Omron Sysmac Studio project OCR_V460H_Example_1.0 (Sysmac Studio 1.54.0.64019, StandardProject)
(* V460-H Application Program Example, based on OCR V460-H Function Blocks (OCR_V460H Library). *)

# Controller new_Controller_0: NX1P2-9024DT1 version 1.46
Task PrimaryTask (priority 4, period or condition 2000): Prg_OCR_V460_All
Library OCR_V460H 1.0.0 (contents left out)

VAR_GLOBAL
    OUT_B00 : BOOL;  (* Output Bit 00 (YELLOW); at BuiltInIO://cpu/#0/Output_Bit_00 *)
    OUT_B01 : BOOL;  (* Output Bit 01 (RED); at BuiltInIO://cpu/#0/Output_Bit_01 *)
    OUT_B02 : BOOL;  (* Output Bit 02 (GREEN); at BuiltInIO://cpu/#0/Output_Bit_02 *)
    V460_01_IN_100 : s_V460_IN_100;  (* EtherNet/IP Input - Assembly 100; network input *)
    V460_01_IN_101 : s_V460_IN_101;  (* EtherNet/IP Input - Assembly 101; network input *)
    V460_01_IN_102 : s_V460_IN_102;  (* EtherNet/IP Input - Assembly 102; network input *)
    V460_01_IN_103 : s_V460_IN_103;  (* EtherNet/IP Input - Assembly 103; network input *)
    V460_01_IN_104 : s_V460_IN_104;  (* EtherNet/IP Input - Assembly 104; network input *)
    V460_01_IN_105 : s_V460_IN_105;  (* EtherNet/IP Input - Assembly 105; network input *)
    V460_01_OUT_197 : s_V460_OUT_197;  (* EtherNet/IP Output - Assembly 197; network output *)
    V460_01_OUT_198 : s_V460_OUT_198;  (* EtherNet/IP Output - Assembly 198; network output *)
    V460_01_Reader_IN : s_V460_Reader_IN := (Reader_IPAddress := '192.168.188.2', Reader_Trigger := False, Reader_ClearCounterNoRead := False, Reader_ClearCounterMatchcode := False);  (* Reader - Input (User) *)
    V460_01_Reader_OUT : s_V460_Reader_OUT;  (* Reader - Output (User) *)
    V460_01_KCommand : s_V460_KCommand;  (* V460-H K Command (User) *)
    V460_01_Control : s_V460_Control;  (* V460-H Control *)
    V460_01_Lighting : s_V460_Lighting;  (* V460-H Lighting *)
    V460_01_Settings : s_V460_Settings;  (* V460-H Settings *)
    V460_01_Database : s_V460_Database;  (* V460-H Database *)
    V460_01_Lighting_HMI : s_V460_Lighting_HMI;  (* V460-H Lighting (HMI) *)
END_VAR

PROGRAM Prg_OCR_V460
VAR
    V460_01_Enable : BOOL := True;  (* V460-H Enable *)
    V460_01_Connected : BOOL;  (* V460-H Connected *)
    V460_01_Busy : BOOL;  (* V460-H Busy *)
    V460_01_Done : BOOL;  (* V460-H Done (Read Cycle Pass) *)
    V460_01_Error : BOOL;  (* V460-H Error (Read Cycle Fail) *)
    V460_01_DecodeLength : UINT;  (* V460-H Decode Length *)
    V460_01_DecodeData : STRING[184];  (* V460-H Decode Data *)
    V460_01_FB_EIP : OCR_V460_EIP;
    V460_01_Timer_ON : TON;  (* V460-H Timer *)
    V460_01_Time_ON : TIME := TIME#200ms;  (* V460-H Time *)
    V460_01_Counter_NoReadCycle : DINT;  (* V460-H Counter No Read Cycle *)
    V460_01_Counter_NoRead : UDINT;  (* V460-H Counter No Read *)
    V460_01_Counter_MismatchCycle : DINT;  (* V460-H Counter Mismatch Cycle *)
    V460_01_Counter_Trigger : UDINT;  (* V460-H Counter Trigger *)
    V460_01_Counter_Matchcode : UDINT;  (* V460-H Counter Matchcode *)
    V460_01_Counter_Mismatch : UDINT;  (* V460-H Counter Mismatch *)
    V460_01_Time_ReadCycleTotal : INT;  (* V460-H Time Read Cycle Total *)
END_VAR
VAR_EXTERNAL
    OUT_B00 : BOOL;
    OUT_B01 : BOOL;
    V460_01_IN_102 : s_V460_IN_102;
    V460_01_OUT_197 : s_V460_OUT_197;
    V460_01_Reader_IN : s_V460_Reader_IN;
    V460_01_Reader_OUT : s_V460_Reader_OUT;
    OUT_B02 : BOOL;
END_VAR

(* Section Prg_OCR_V460: ladder, written here as Structured Text *)

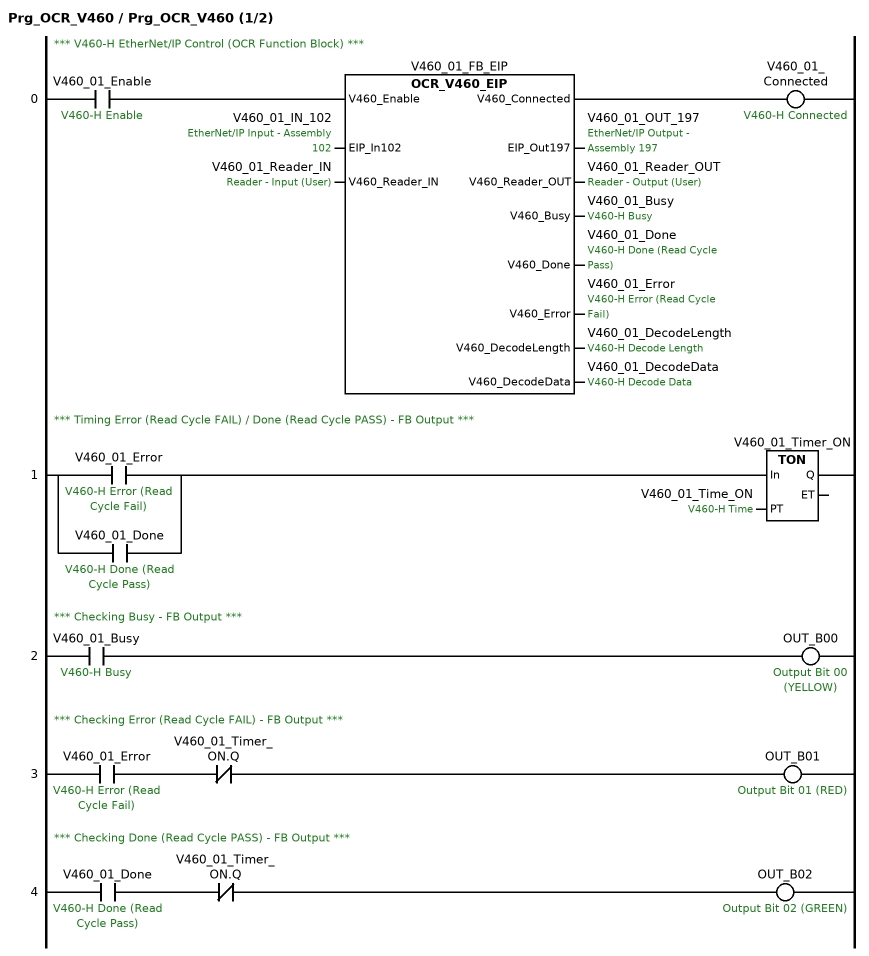
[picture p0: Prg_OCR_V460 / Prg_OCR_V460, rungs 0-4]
(* Rung 0: *** V460-H EtherNet/IP Control (OCR Function Block) *** *)
V460_01_FB_EIP(V460_Enable := V460_01_Enable, EIP_In102 := V460_01_IN_102, V460_Reader_IN := V460_01_Reader_IN, EIP_Out197 => V460_01_OUT_197, V460_Reader_OUT => V460_01_Reader_OUT, V460_Busy => V460_01_Busy, V460_Done => V460_01_Done, V460_Error => V460_01_Error, V460_DecodeLength => V460_01_DecodeLength, V460_DecodeData => V460_01_DecodeData);
V460_01_Connected := V460_01_FB_EIP.V460_Connected;
(* Rung 1: *** Timing Error (Read Cycle FAIL) / Done (Read Cycle PASS) - FB Output *** *)
V460_01_Timer_ON(In := V460_01_Error OR V460_01_Done, PT := V460_01_Time_ON);
(* Rung 2: *** Checking Busy - FB Output *** *)
OUT_B00 := V460_01_Busy;
(* Rung 3: *** Checking Error (Read Cycle FAIL) - FB Output *** *)
OUT_B01 := V460_01_Error AND NOT V460_01_Timer_ON.Q;
(* Rung 4: *** Checking Done (Read Cycle PASS) - FB Output *** *)
OUT_B02 := V460_01_Done AND NOT V460_01_Timer_ON.Q;

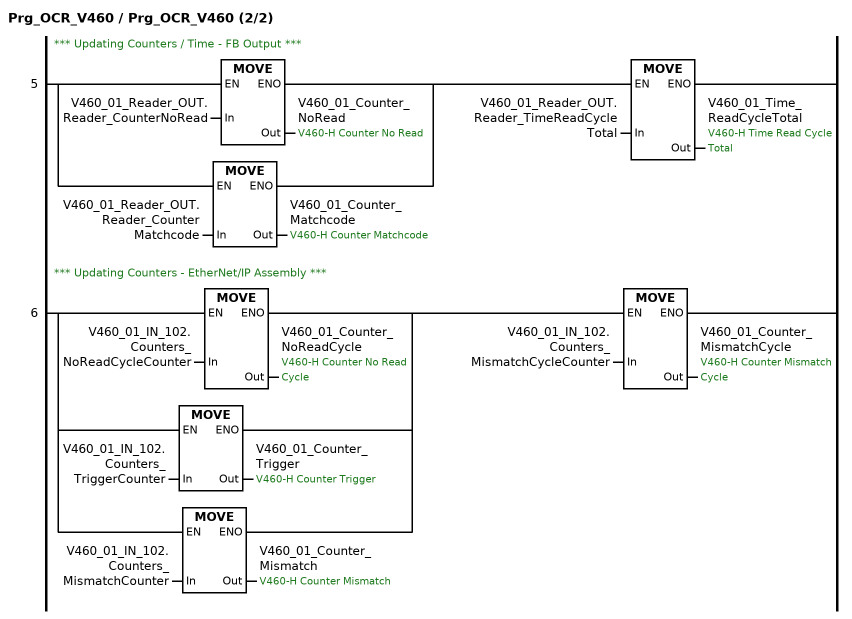
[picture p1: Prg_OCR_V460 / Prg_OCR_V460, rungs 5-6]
(* Rung 5: *** Updating Counters / Time - FB Output *** *)
V460_01_Counter_NoRead := V460_01_Reader_OUT.Reader_CounterNoRead;
V460_01_Counter_Matchcode := V460_01_Reader_OUT.Reader_CounterMatchcode;
V460_01_Time_ReadCycleTotal := V460_01_Reader_OUT.Reader_TimeReadCycleTotal;
(* Rung 6: *** Updating Counters - EtherNet/IP Assembly *** *)
V460_01_Counter_NoReadCycle := V460_01_IN_102.Counters_NoReadCycleCounter;
V460_01_Counter_Trigger := V460_01_IN_102.Counters_TriggerCounter;
V460_01_Counter_Mismatch := V460_01_IN_102.Counters_MismatchCounter;
V460_01_Counter_MismatchCycle := V460_01_IN_102.Counters_MismatchCycleCounter;
END_PROGRAM

PROGRAM Prg_OCR_V460_All
VAR
    V460_01_Enable : BOOL := True;  (* V460-H Enable *)
    V460_01_Connected : BOOL;  (* V460-H Connected *)
    V460_01_Busy : BOOL;  (* V460-H Busy *)
    V460_01_Done : BOOL;  (* V460-H Done (Read Cycle Pass) *)
    V460_01_Error : BOOL;  (* V460-H Error (Read Cycle Fail) *)
    V460_01_DecodeLength : UINT;  (* V460-H Decode Length *)
    V460_01_DecodeData : STRING[184];  (* V460-H Decode Data *)
    V460_01_KCommand_Busy : BOOL;  (* V460-H K Command Busy *)
    V460_01_KCommand_Done : BOOL;  (* V460-H K Command Done *)
    V460_01_KCommand_Error : BOOL;  (* V460-H K Command Error *)
    V460_01_Control_Busy : BOOL;  (* V460-H Control Busy *)
    V460_01_Control_Done : BOOL;  (* V460-H Control Done *)
    V460_01_Control_Error : BOOL;  (* V460-H Control Error *)
    V460_01_Lighting_Busy : BOOL;  (* V460-H Lighting Busy *)
    V460_01_Lighting_Done : BOOL;  (* V460-H Lighting Done *)
    V460_01_Lighting_Error : BOOL;  (* V460-H Lighting Error *)
    V460_01_Settings_Busy : BOOL;  (* V460-H Settings Busy *)
    V460_01_Settings_Done : BOOL;  (* V460-H Settings Done *)
    V460_01_Settings_Error : BOOL;  (* V460-H Settings Error *)
    V460_01_Database_Busy : BOOL;  (* V460-H Database Busy *)
    V460_01_Database_Done : BOOL;  (* V460-H Database Done *)
    V460_01_Database_Error : BOOL;  (* V460-H Database Error *)
    V460_01_FB_EIP : OCR_V460_EIP;
    V460_01_FB_KCommand : OCR_V460_KCommand;
    V460_01_FB_Control : OCR_V460_Control;
    V460_01_FB_Lighting : OCR_V460_Lighting;
    V460_01_FB_Settings : OCR_V460_Settings;
    V460_01_FB_Database : OCR_V460_Database;
    V460_01_KCommand : s_V460_KCommand;  (* V460-H K Command (User) *)
    V460_01_Control : s_V460_Control;  (* V460-H Control *)
    V460_01_Settings : s_V460_Settings;  (* V460-H Settings *)
    V460_01_Settings_HMI : s_V460_Settings_HMI;  (* V460-H Settings (HMI) *)
    V460_01_Database : s_V460_Database;  (* V460-H Database *)
    V460_01_Timer_ON : TON;  (* V460-H Timer *)
    V460_01_Time_ON : TIME := TIME#200ms;  (* V460-H Time *)
    V460_01_Counter_NoReadCycle : DINT;  (* V460-H Counter No Read Cycle *)
    V460_01_Counter_NoRead : UDINT;  (* V460-H Counter No Read *)
    V460_01_Counter_MismatchCycle : DINT;  (* V460-H Counter Mismatch Cycle *)
    V460_01_Counter_Trigger : UDINT;  (* V460-H Counter Trigger *)
    V460_01_Counter_Matchcode : UDINT;  (* V460-H Counter Matchcode *)
    V460_01_Counter_Mismatch : UDINT;  (* V460-H Counter Mismatch *)
    V460_01_Time_ReadCycleTotal : INT;  (* V460-H Time Read Cycle Total *)
END_VAR
VAR_EXTERNAL
    OUT_B00 : BOOL;
    OUT_B01 : BOOL;
    V460_01_IN_102 : s_V460_IN_102;
    V460_01_OUT_197 : s_V460_OUT_197;
    V460_01_Reader_IN : s_V460_Reader_IN;
    V460_01_Reader_OUT : s_V460_Reader_OUT;
    OUT_B02 : BOOL;
    V460_01_Lighting : s_V460_Lighting;
    V460_01_Lighting_HMI : s_V460_Lighting_HMI;
END_VAR

(* Section Prg_OCR_V460_All: ladder, written here as Structured Text *)

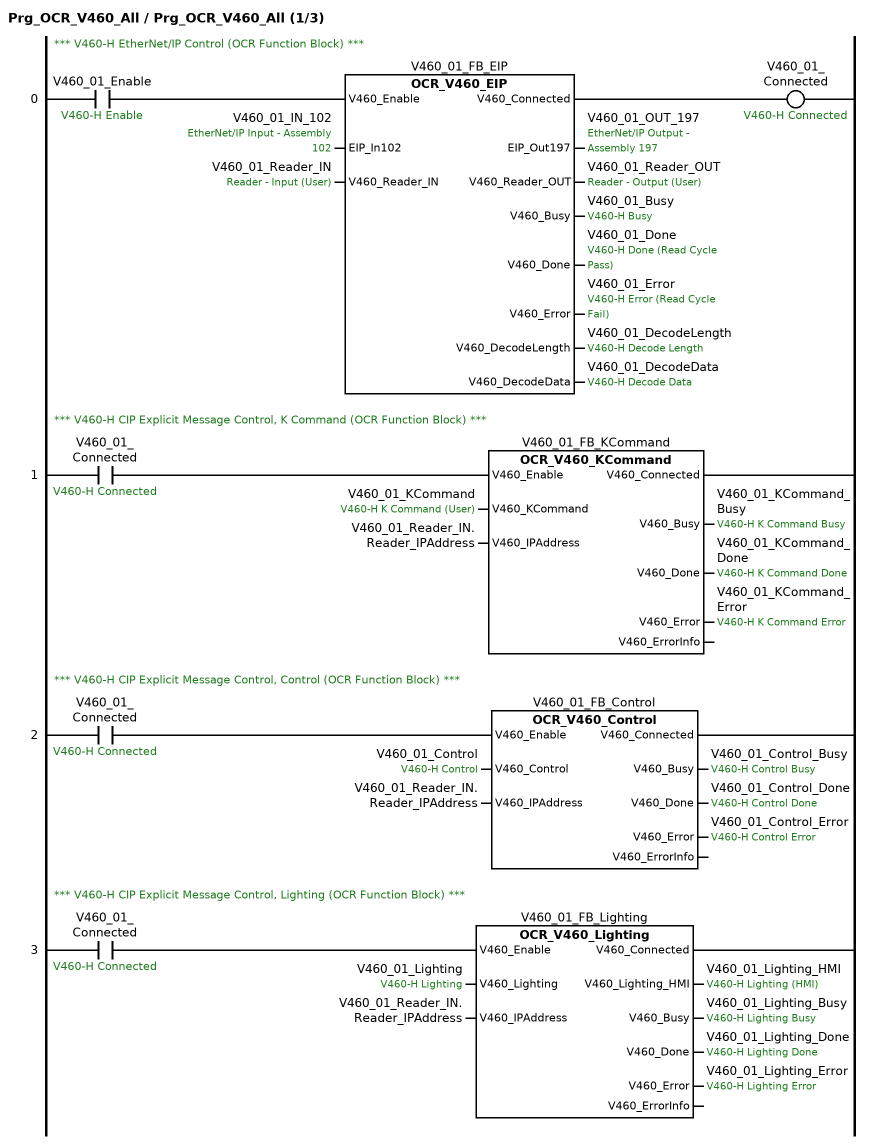
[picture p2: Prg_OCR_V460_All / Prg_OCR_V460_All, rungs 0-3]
(* Rung 0: *** V460-H EtherNet/IP Control (OCR Function Block) *** *)
V460_01_FB_EIP(V460_Enable := V460_01_Enable, EIP_In102 := V460_01_IN_102, V460_Reader_IN := V460_01_Reader_IN, EIP_Out197 => V460_01_OUT_197, V460_Reader_OUT => V460_01_Reader_OUT, V460_Busy => V460_01_Busy, V460_Done => V460_01_Done, V460_Error => V460_01_Error, V460_DecodeLength => V460_01_DecodeLength, V460_DecodeData => V460_01_DecodeData);
V460_01_Connected := V460_01_FB_EIP.V460_Connected;
(* Rung 1: *** V460-H CIP Explicit Message Control, K Command (OCR Function Block) *** *)
V460_01_FB_KCommand(V460_Enable := V460_01_Connected, V460_KCommand := V460_01_KCommand, V460_IPAddress := V460_01_Reader_IN.Reader_IPAddress, V460_Busy => V460_01_KCommand_Busy, V460_Done => V460_01_KCommand_Done, V460_Error => V460_01_KCommand_Error);
(* Rung 2: *** V460-H CIP Explicit Message Control, Control (OCR Function Block) *** *)
V460_01_FB_Control(V460_Enable := V460_01_Connected, V460_Control := V460_01_Control, V460_IPAddress := V460_01_Reader_IN.Reader_IPAddress, V460_Busy => V460_01_Control_Busy, V460_Done => V460_01_Control_Done, V460_Error => V460_01_Control_Error);
(* Rung 3: *** V460-H CIP Explicit Message Control, Lighting (OCR Function Block) *** *)
V460_01_FB_Lighting(V460_Enable := V460_01_Connected, V460_Lighting := V460_01_Lighting, V460_IPAddress := V460_01_Reader_IN.Reader_IPAddress, V460_Lighting_HMI => V460_01_Lighting_HMI, V460_Busy => V460_01_Lighting_Busy, V460_Done => V460_01_Lighting_Done, V460_Error => V460_01_Lighting_Error);

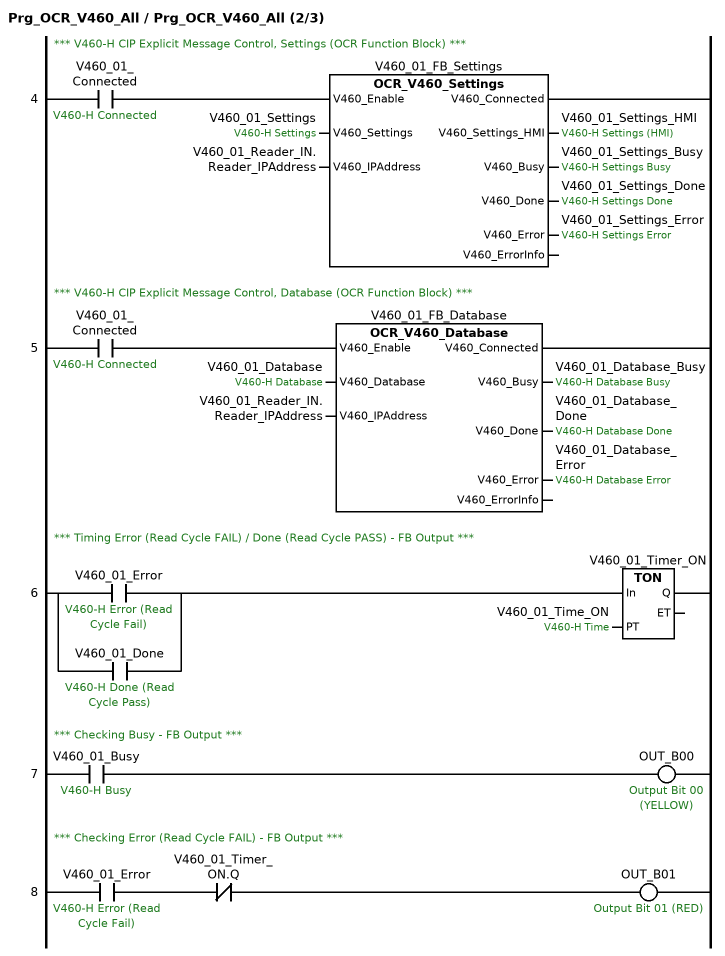
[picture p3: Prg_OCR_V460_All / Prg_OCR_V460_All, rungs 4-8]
(* Rung 4: *** V460-H CIP Explicit Message Control, Settings (OCR Function Block) *** *)
V460_01_FB_Settings(V460_Enable := V460_01_Connected, V460_Settings := V460_01_Settings, V460_IPAddress := V460_01_Reader_IN.Reader_IPAddress, V460_Settings_HMI => V460_01_Settings_HMI, V460_Busy => V460_01_Settings_Busy, V460_Done => V460_01_Settings_Done, V460_Error => V460_01_Settings_Error);
(* Rung 5: *** V460-H CIP Explicit Message Control, Database (OCR Function Block) *** *)
V460_01_FB_Database(V460_Enable := V460_01_Connected, V460_Database := V460_01_Database, V460_IPAddress := V460_01_Reader_IN.Reader_IPAddress, V460_Busy => V460_01_Database_Busy, V460_Done => V460_01_Database_Done, V460_Error => V460_01_Database_Error);
(* Rung 6: *** Timing Error (Read Cycle FAIL) / Done (Read Cycle PASS) - FB Output *** *)
V460_01_Timer_ON(In := V460_01_Error OR V460_01_Done, PT := V460_01_Time_ON);
(* Rung 7: *** Checking Busy - FB Output *** *)
OUT_B00 := V460_01_Busy;
(* Rung 8: *** Checking Error (Read Cycle FAIL) - FB Output *** *)
OUT_B01 := V460_01_Error AND NOT V460_01_Timer_ON.Q;

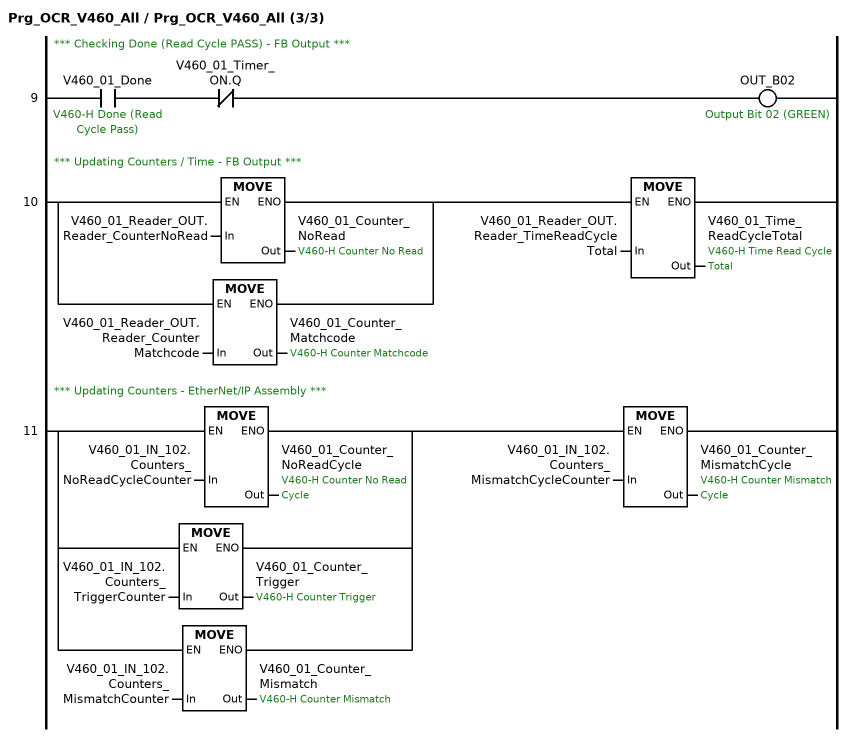
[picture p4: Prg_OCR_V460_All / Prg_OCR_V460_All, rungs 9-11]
(* Rung 9: *** Checking Done (Read Cycle PASS) - FB Output *** *)
OUT_B02 := V460_01_Done AND NOT V460_01_Timer_ON.Q;
(* Rung 10: *** Updating Counters / Time - FB Output *** *)
V460_01_Counter_NoRead := V460_01_Reader_OUT.Reader_CounterNoRead;
V460_01_Counter_Matchcode := V460_01_Reader_OUT.Reader_CounterMatchcode;
V460_01_Time_ReadCycleTotal := V460_01_Reader_OUT.Reader_TimeReadCycleTotal;
(* Rung 11: *** Updating Counters - EtherNet/IP Assembly *** *)
V460_01_Counter_NoReadCycle := V460_01_IN_102.Counters_NoReadCycleCounter;
V460_01_Counter_Trigger := V460_01_IN_102.Counters_TriggerCounter;
V460_01_Counter_Mismatch := V460_01_IN_102.Counters_MismatchCounter;
V460_01_Counter_MismatchCycle := V460_01_IN_102.Counters_MismatchCycleCounter;
END_PROGRAM

PROGRAM Pgr_OCR_V460_EIP_105
VAR
    V460_01_Enable : BOOL := True;  (* V460-H Enable *)
    V460_01_Connected : BOOL;  (* V460-H Connected *)
    V460_01_Busy : BOOL;  (* V460-H Busy *)
    V460_01_Done : BOOL;  (* V460-H Done (Read Cycle Pass) *)
    V460_01_Error : BOOL;  (* V460-H Error (Read Cycle Fail) *)
    V460_01_TotalCodes : SINT;  (* V460-H Decodes Total *)
    V460_01_Decode01 : s_V460_DecodeInfo;  (* V460-H Decode Info 01 *)
    V460_01_Decode02 : s_V460_DecodeInfo;  (* V460-H Decode Info 02 *)
    V460_01_Decode03 : s_V460_DecodeInfo;  (* V460-H Decode Info 03 *)
    V460_01_Decode04 : s_V460_DecodeInfo;  (* V460-H Decode Info 04 *)
    V460_01_Decode05 : s_V460_DecodeInfo;  (* V460-H Decode Info 05 *)
    V460_01_Decode06 : s_V460_DecodeInfo;  (* V460-H Decode Info 06 *)
    V460_01_Decode07 : s_V460_DecodeInfo;  (* V460-H Decode Info 07 *)
    V460_01_Decode08 : s_V460_DecodeInfo;  (* V460-H Decode Info 08 *)
    V460_01_Decode09 : s_V460_DecodeInfo;  (* V460-H Decode Info 09 *)
    V460_01_Decode10 : s_V460_DecodeInfo;  (* V460-H Decode Info 10 *)
    V460_01_FB_EIP : OCR_V460_EIP_105;
    V460_01_Timer_ON : TON;  (* V460-H Timer *)
    V460_01_Time_ON : TIME := TIME#200ms;
    V460_01_Counter_NoReadCycle : DINT;  (* V460-H Counter No Read Cycle *)
    V460_01_Counter_NoRead : UDINT;  (* V460-H Counter No Read *)
    V460_01_Counter_MismatchCycle : DINT;  (* V460-H Counter Mismatch Cycle *)
    V460_01_Counter_Trigger : UDINT;  (* V460-H Counter Trigger *)
    V460_01_Counter_Matchcode : UDINT;  (* V460-H Counter Matchcode *)
    V460_01_Counter_Mismatch : UDINT;  (* V460-H Counter Mismatch *)
END_VAR
VAR_EXTERNAL
    OUT_B00 : BOOL;
    OUT_B01 : BOOL;
    V460_01_IN_105 : s_V460_IN_105;
    V460_01_OUT_197 : s_V460_OUT_197;
    V460_01_Reader_IN : s_V460_Reader_IN;
    OUT_B02 : BOOL;
END_VAR

(* Section Pgr_OCR_V460_EIP_105: ladder, written here as Structured Text *)

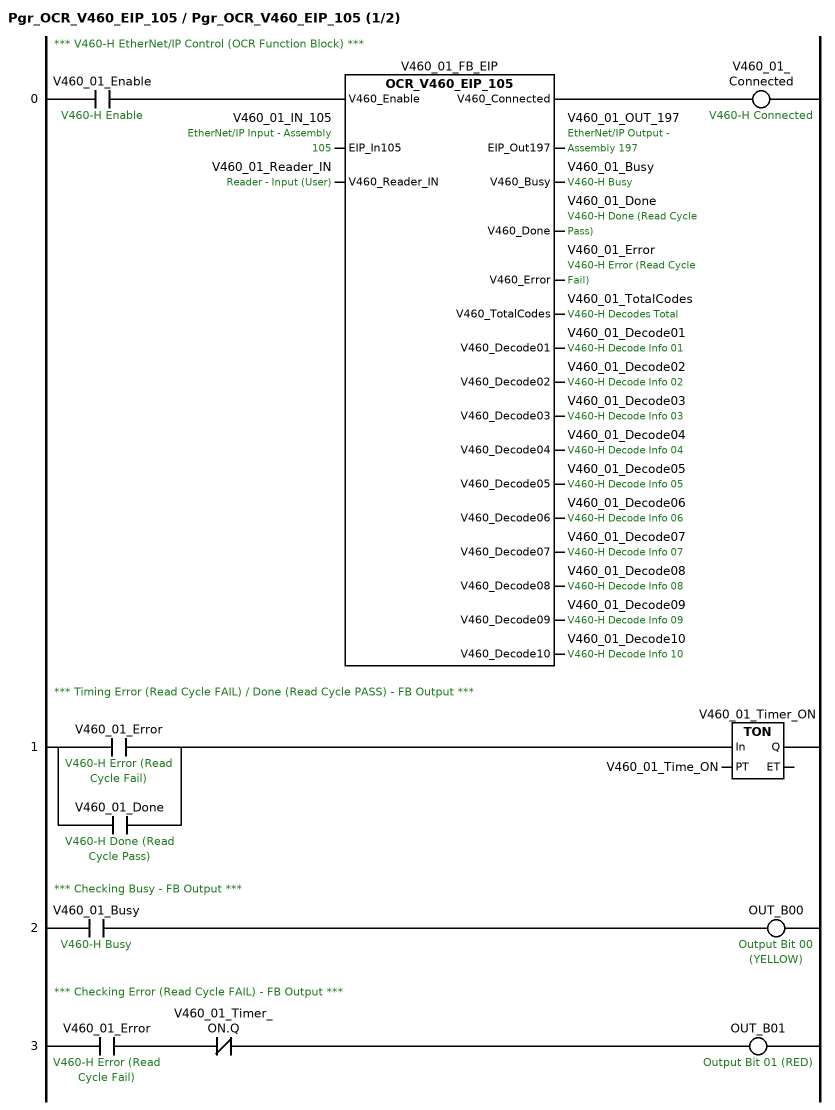
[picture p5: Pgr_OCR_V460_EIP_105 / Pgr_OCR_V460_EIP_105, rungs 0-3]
(* Rung 0: *** V460-H EtherNet/IP Control (OCR Function Block) *** *)
V460_01_FB_EIP(V460_Enable := V460_01_Enable, EIP_In105 := V460_01_IN_105, V460_Reader_IN := V460_01_Reader_IN, EIP_Out197 => V460_01_OUT_197, V460_Busy => V460_01_Busy, V460_Done => V460_01_Done, V460_Error => V460_01_Error, V460_TotalCodes => V460_01_TotalCodes, V460_Decode01 => V460_01_Decode01, V460_Decode02 => V460_01_Decode02, V460_Decode03 => V460_01_Decode03, V460_Decode04 => V460_01_Decode04, V460_Decode05 => V460_01_Decode05, V460_Decode06 => V460_01_Decode06, V460_Decode07 => V460_01_Decode07, V460_Decode08 => V460_01_Decode08, V460_Decode09 => V460_01_Decode09, V460_Decode10 => V460_01_Decode10);
V460_01_Connected := V460_01_FB_EIP.V460_Connected;
(* Rung 1: *** Timing Error (Read Cycle FAIL) / Done (Read Cycle PASS) - FB Output *** *)
V460_01_Timer_ON(In := V460_01_Error OR V460_01_Done, PT := V460_01_Time_ON);
(* Rung 2: *** Checking Busy - FB Output *** *)
OUT_B00 := V460_01_Busy;
(* Rung 3: *** Checking Error (Read Cycle FAIL) - FB Output *** *)
OUT_B01 := V460_01_Error AND NOT V460_01_Timer_ON.Q;

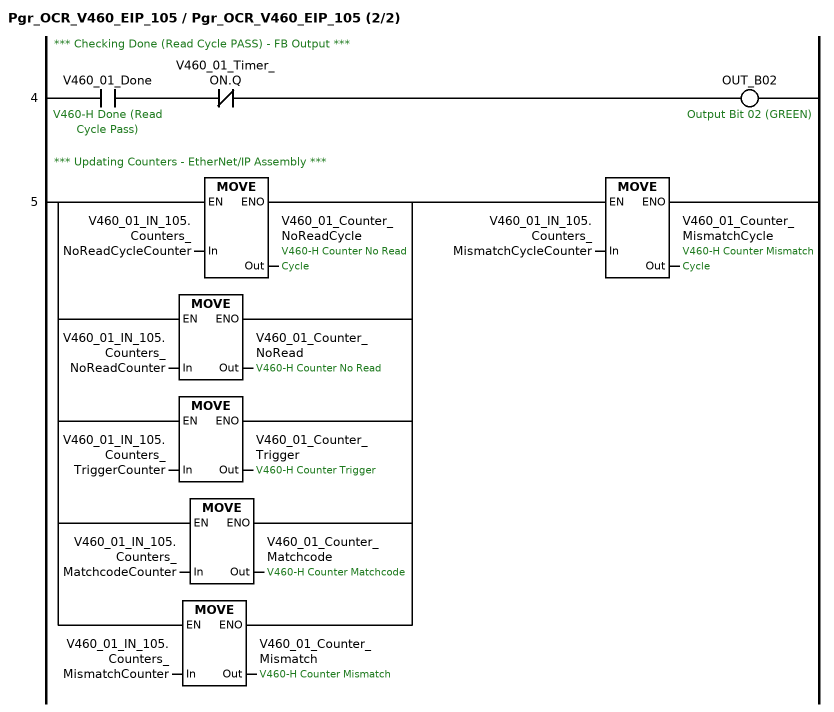
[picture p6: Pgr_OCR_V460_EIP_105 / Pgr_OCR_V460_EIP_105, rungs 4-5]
(* Rung 4: *** Checking Done (Read Cycle PASS) - FB Output *** *)
OUT_B02 := V460_01_Done AND NOT V460_01_Timer_ON.Q;
(* Rung 5: *** Updating Counters - EtherNet/IP Assembly *** *)
V460_01_Counter_NoReadCycle := V460_01_IN_105.Counters_NoReadCycleCounter;
V460_01_Counter_NoRead := V460_01_IN_105.Counters_NoReadCounter;
V460_01_Counter_Trigger := V460_01_IN_105.Counters_TriggerCounter;
V460_01_Counter_Matchcode := V460_01_IN_105.Counters_MatchcodeCounter;
V460_01_Counter_Mismatch := V460_01_IN_105.Counters_MismatchCounter;
V460_01_Counter_MismatchCycle := V460_01_IN_105.Counters_MismatchCycleCounter;
END_PROGRAM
